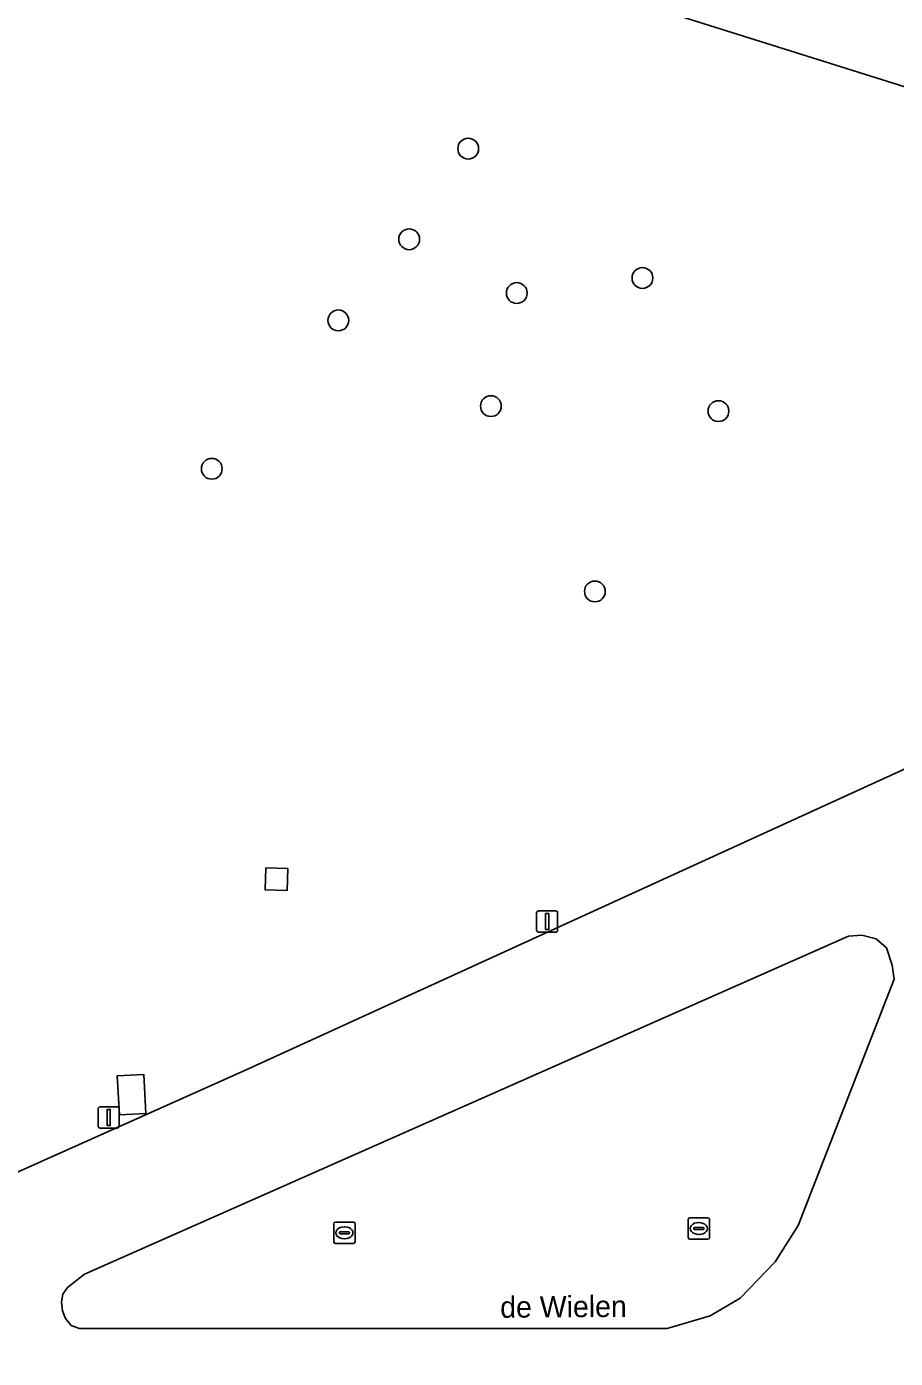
# Model space of a CAD drawing. Extents: x 161477 to 163040, y 383680 to 384871.
# Drawn here: x 161755 to 161795.8, y 384192.2 to 384254.7 of the extents above; entities that cross this region are included whole.
import ezdxf

# ---------------------------------------------------------------- set-up
doc = ezdxf.new("R2010")
doc.units = 0
for name, color, linetype in [('IMGEO_Boom', 7, 'Continuous'), ('IMGEO_Groenvoorziening', 7, 'Continuous'), ('IMGEO_Lage_trafo', 7, 'Continuous'), ('IMGEO_Lichtmast', 7, 'Continuous'), ('IMGEO_Openbare_ruimte_label', 7, 'Continuous'), ('IMGEO_Rijbaan_lokaal_gesloten', 7, 'Continuous'), ('IMGEO_Rioolput', 7, 'Continuous'), ('IMGEO_Voetpad_gesloten', 7, 'Continuous')]:
    doc.layers.add(name, color=color, linetype=linetype)

msp = doc.modelspace()

# ---------------------------------------------------------------- linework, layer by layer
at = {"layer": 'IMGEO_Boom'}
for centre in [(161775.696, 384248.985), (161772.921, 384244.729), (161783.878, 384242.91), (161777.975, 384242.204), (161769.594, 384240.919), (161776.761, 384236.894), (161787.45, 384236.66), (161763.649, 384233.95), (161781.646, 384228.19)]:
    msp.add_circle(centre, 0.489, dxfattribs=at)
at = {"layer": 'IMGEO_Groenvoorziening'}
msp.add_lwpolyline([(161734.934, 384192.171), (161765.263, 384205.726), (161800.806, 384221.962), (161803.993, 384223.644), (161805.847, 384225.201), (161807.757, 384227.377), (161809.351, 384229.582), (161810.252, 384232.34), (161810.827, 384235.617), (161810.562, 384238.772), (161809.809, 384241.12), (161808.636, 384243.002), (161806.876, 384245.277), (161804.691, 384247.773), (161802.793, 384249.215), (161801.197, 384250.04), (161798.102, 384251.287), (161756.674, 384264.323)], dxfattribs=at)
for points in [[(161767.223, 384215.18), (161767.198, 384214.147), (161766.158, 384214.173), (161766.183, 384215.206)], [(161756.87, 384195.493), (161756.646, 384195.189), (161756.588, 384194.827), (161756.632, 384194.408), (161756.784, 384194.047), (161757.044, 384193.721), (161757.44, 384193.567), (161785.033, 384193.567), (161787.06, 384194.165), (161788.477, 384195.006), (161790.115, 384196.711), (161791.199, 384198.416), (161795.707, 384209.98), (161795.613, 384210.631), (161795.338, 384211.448), (161794.854, 384211.875), (161794.189, 384212.041), (161793.552, 384212.004), (161757.674, 384196.129)], [(161760.452, 384205.503), (161760.555, 384203.67), (161759.307, 384203.601), (161759.204, 384205.434)]]:
    msp.add_lwpolyline(points, close=True, dxfattribs=at)
at = {"layer": 'IMGEO_Lage_trafo'}
msp.add_lwpolyline([(161759.307, 384203.601), (161760.555, 384203.67), (161760.452, 384205.503), (161759.204, 384205.434)], close=True, dxfattribs=at)
at = {"layer": 'IMGEO_Lichtmast'}
for p, q in [((161778.907, 384212.284), (161778.907, 384213.084)), ((161778.907, 384213.084), (161778.907, 384212.284)), ((161779.007, 384213.184), (161779.797, 384213.184)), ((161779.797, 384213.184), (161779.007, 384213.184)), ((161779.897, 384213.084), (161779.897, 384212.284)), ((161779.897, 384212.284), (161779.897, 384213.084)), ((161779.797, 384212.184), (161779.007, 384212.184)), ((161779.007, 384212.184), (161779.797, 384212.184)), ((161758.309, 384203.087), (161758.309, 384203.887)), ((161758.309, 384203.887), (161758.309, 384203.087)), ((161758.409, 384203.987), (161759.199, 384203.987)), ((161759.199, 384203.987), (161758.409, 384203.987)), ((161759.299, 384203.887), (161759.299, 384203.087)), ((161759.299, 384203.087), (161759.299, 384203.887)), ((161759.199, 384202.987), (161758.409, 384202.987)), ((161758.409, 384202.987), (161759.199, 384202.987))]:
    msp.add_line(p, q, dxfattribs=at)
for points in [[(161779.327, 384213.059), (161779.477, 384213.059), (161779.477, 384212.309), (161779.327, 384212.309), (161779.327, 384213.059)], [(161758.729, 384203.862), (161758.879, 384203.862), (161758.879, 384203.112), (161758.729, 384203.112), (161758.729, 384203.862)]]:
    msp.add_lwpolyline(points, dxfattribs=at)
for centre, start, end in [((161779.007, 384213.084), 90, 180), ((161779.007, 384213.084), 90, 180), ((161779.797, 384213.084), 0, 90), ((161779.797, 384213.084), 360, 90), ((161779.007, 384212.284), 180, 270), ((161779.007, 384212.284), 180, 270), ((161779.797, 384212.284), 270, 0), ((161779.797, 384212.284), 270, 0), ((161758.409, 384203.887), 90, 180), ((161758.409, 384203.887), 90, 180), ((161759.199, 384203.887), 0, 90), ((161759.199, 384203.887), 360, 90), ((161758.409, 384203.087), 180, 270), ((161758.409, 384203.087), 180, 270), ((161759.199, 384203.087), 270, 0), ((161759.199, 384203.087), 270, 0)]:
    msp.add_arc(centre, 0.1, start, end, dxfattribs=at)
at = {"layer": 'IMGEO_Rijbaan_lokaal_gesloten'}
msp.add_lwpolyline([(161756.674, 384264.323), (161798.102, 384251.287), (161801.197, 384250.04), (161802.793, 384249.215), (161804.691, 384247.773), (161806.876, 384245.277), (161808.636, 384243.002), (161809.809, 384241.12), (161810.562, 384238.772), (161810.827, 384235.617), (161810.252, 384232.34), (161809.351, 384229.582), (161807.757, 384227.377), (161805.847, 384225.201), (161803.993, 384223.644), (161800.806, 384221.962), (161765.263, 384205.726), (161734.934, 384192.171)], dxfattribs=at)
msp.add_lwpolyline([(161756.87, 384195.493), (161757.674, 384196.129), (161793.552, 384212.004), (161794.189, 384212.041), (161794.854, 384211.875), (161795.338, 384211.448), (161795.613, 384210.631), (161795.707, 384209.98), (161791.199, 384198.416), (161790.115, 384196.711), (161788.477, 384195.006), (161787.06, 384194.165), (161785.033, 384193.567), (161757.44, 384193.567), (161757.044, 384193.721), (161756.784, 384194.047), (161756.632, 384194.408), (161756.588, 384194.827), (161756.646, 384195.189)], close=True, dxfattribs=at)
at = {"layer": 'IMGEO_Rioolput'}
for p, q in [((161769.454, 384198.57), (161770.306, 384198.57)), ((161786.029, 384197.844), (161786.029, 384198.696)), ((161786.104, 384198.77), (161786.956, 384198.77)), ((161786.517, 384198.55), (161786.542, 384198.55)), ((161787.03, 384198.696), (161787.03, 384197.844)), ((161769.379, 384197.644), (161769.379, 384198.496)), ((161769.638, 384198.064), (161769.638, 384198.076)), ((161770.076, 384198.027), (161769.678, 384198.027)), ((161769.681, 384198.113), (161770.079, 384198.113)), ((161769.867, 384198.35), (161769.892, 384198.35)), ((161770.122, 384198.076), (161770.122, 384198.064)), ((161770.38, 384198.496), (161770.38, 384197.644)), ((161786.288, 384198.264), (161786.288, 384198.276)), ((161786.726, 384198.227), (161786.328, 384198.227)), ((161786.331, 384198.313), (161786.729, 384198.313)), ((161786.54, 384197.99), (161786.515, 384197.99)), ((161786.772, 384198.276), (161786.772, 384198.264)), ((161770.306, 384197.57), (161769.454, 384197.57)), ((161769.89, 384197.79), (161769.865, 384197.79)), ((161786.956, 384197.77), (161786.104, 384197.77))]:
    msp.add_line(p, q, dxfattribs=at)
for points in [[(161769.454, 384198.57), (161770.306, 384198.57)], [(161786.029, 384197.844), (161786.029, 384198.696)], [(161786.104, 384198.77), (161786.956, 384198.77)], [(161787.03, 384198.696), (161787.03, 384197.844)], [(161769.379, 384197.644), (161769.379, 384198.496)], [(161770.38, 384198.496), (161770.38, 384197.644)], [(161770.306, 384197.57), (161769.454, 384197.57)], [(161786.956, 384197.77), (161786.104, 384197.77)]]:
    msp.add_lwpolyline(points, dxfattribs=at)
for centre, radius, start, end in [((161769.456, 384198.494), 0.0765, 91.55205, 178.44795), ((161769.456, 384198.494), 0.0765, 91.55205, 178.44795), ((161770.304, 384198.494), 0.0765, 1.55205, 88.44795), ((161770.304, 384198.494), 0.0765, 1.55205, 88.44795), ((161786.106, 384198.694), 0.0765, 91.55205, 178.44795), ((161786.106, 384198.694), 0.0765, 91.55205, 178.44795), ((161786.954, 384198.694), 0.0765, 1.55205, 88.44795), ((161786.954, 384198.694), 0.0765, 1.55205, 88.44795), ((161769.678, 384198.073), 0.0403, 85.87752, 175.75265), ((161769.675, 384198.063), 0.0366, 178.93798, 274.71019), ((161770.079, 384198.07), 0.043, 264.86636, 352.45326), ((161770.083, 384198.075), 0.0386, 1.73085, 96.63898), ((161786.328, 384198.273), 0.0403, 85.87752, 175.75265), ((161786.325, 384198.263), 0.0366, 178.93798, 274.71019), ((161786.729, 384198.27), 0.043, 264.86636, 352.45326), ((161786.733, 384198.275), 0.0386, 1.73085, 96.63898), ((161769.456, 384197.646), 0.0765, 181.55205, 268.44795), ((161769.456, 384197.646), 0.0765, 181.55205, 268.44795), ((161770.304, 384197.646), 0.0765, 271.55205, 358.44795), ((161770.304, 384197.646), 0.0765, 271.55205, 358.44795), ((161786.106, 384197.846), 0.0765, 181.55205, 268.44795), ((161786.106, 384197.846), 0.0765, 181.55205, 268.44795), ((161786.954, 384197.846), 0.0765, 271.55205, 358.44795), ((161786.954, 384197.846), 0.0765, 271.55205, 358.44795)]:
    msp.add_arc(centre, radius, start, end, dxfattribs=at)
for centre, major_axis, ratio, start_param, end_param in [((161786.516, 384198.27), (-0.387, 0.002), 0.722429, 4.712389, 7.853982), ((161786.541, 384198.27), (-0.39, 0.002), 0.717154, 1.570796, 4.712389), ((161769.866, 384198.07), (-0.387, 0.002), 0.722429, 4.712389, 7.853982), ((161769.891, 384198.07), (-0.39, 0.002), 0.717154, 1.570796, 4.712389)]:
    msp.add_ellipse(centre, major_axis=major_axis, ratio=ratio, start_param=start_param, end_param=end_param, dxfattribs=at)
at = {"layer": 'IMGEO_Voetpad_gesloten'}
msp.add_lwpolyline([(161767.223, 384215.18), (161766.183, 384215.206), (161766.158, 384214.173), (161767.198, 384214.147)], close=True, dxfattribs=at)

# ---------------------------------------------------------------- texts
at = {"layer": 'IMGEO_Openbare_ruimte_label'}
msp.add_text('de Wielen', height=1, rotation=0.40106, dxfattribs=at).set_placement((161777.2, 384194.078))

doc.saveas('drawing.dxf')
